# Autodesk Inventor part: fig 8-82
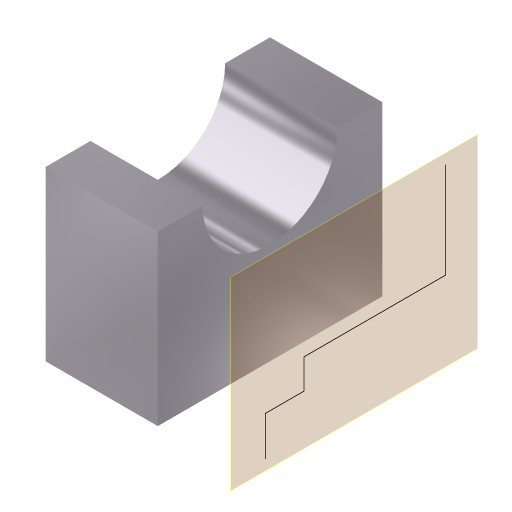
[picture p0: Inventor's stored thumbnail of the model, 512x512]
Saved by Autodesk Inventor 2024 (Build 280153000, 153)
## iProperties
Shininess: 77.0
Length Units: 11269
Angle Units: 11279
Time Units: 11290
Mass Units: 11283
Length Display Precision: 3
Angle Display Precision: 2
Created: 2002-01
Part Number: fig 8-82
Document SubType Name: Modeling
Designer: ***
Density: 1 g/cm^3
Material: Generic
Appearance: Metal-AL-6061 (Polished)
Density: 0.0
Volumn: 0.0
Area: 0.0
PropertySet Name: Model Information
Control State: 0
Master: False
Checked Out: False
Author: ***
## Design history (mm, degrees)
sketch "Sketch5"
  geometry: L1 (-22.226, 10.275)-(-14.226, 10.275); L2 (9.774, 10.275)-(17.774, 10.275); L3 (17.774, 10.275)-(17.774, -19.725); L4 (17.774, -19.725)-(-22.226, -19.725); L5 (-22.226, -19.725)-(-22.226, 10.275); A1 r 12 centre (-2.226, 10.275) between (-14.226, 10.275) and (9.774, 10.275)
  constraints: 10 end point, 2 equal length, 2 parallel, 2 point on circle, 1 centre point, 1 collinear, 1 horizontal, 1 perpendicular, 1 point on line
  dimensions: "d7" = 40 distance of L3.end L4.end; "d8" = 30 distance of L2.end L3.end; "d9" = 12 radius of A1
extrude "Extrusion2" new body sketch "Sketch5" distance "d10" = 20; taper "d11" = 0 deg
workplane "Work Plane3"
sketch "Sketch6"
  geometry: L1 (19.321, -18.091)-(12.314, -18.091); L2 (12.314, -18.091)-(12.314, -11.217); L3 (12.314, -11.217)-(7.026, -11.217); L4 (7.026, -11.217)-(7.026, 7.425); L5 (7.026, 7.425)-(7.026, 14.035); L6 (7.026, 14.035)-(-10.029, 14.035)
  constraints: 12 end point, 4 parallel, 1 horizontal, 1 perpendicular
body "Solid1"
other parameters: "d12" = 15
